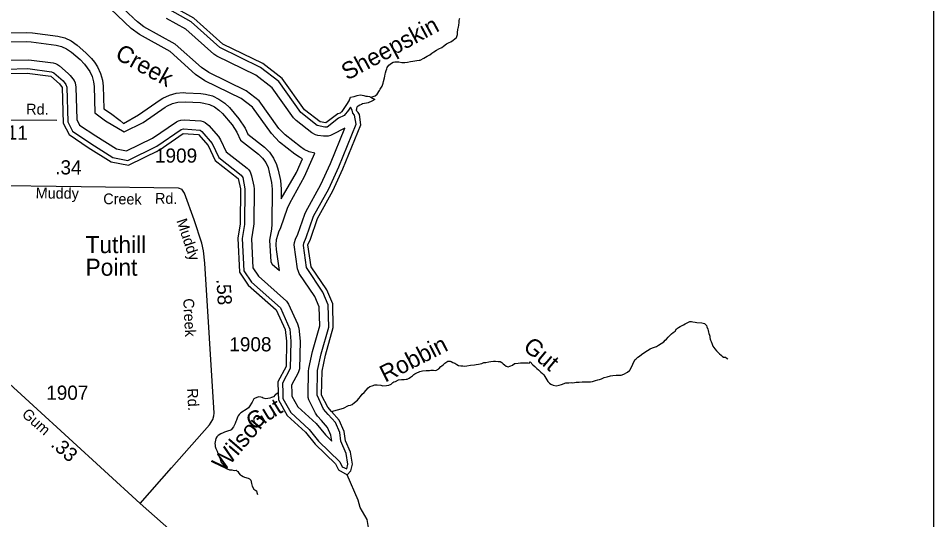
# Model space of a CAD drawing. Extents: x 2532689 to 2764727, y 536648 to 732970.
# Drawn here: x 2687851 to 2695930, y 582198 to 586621 of the extents above; entities that cross this region are included whole.
import ezdxf

# ---------------------------------------------------------------- set-up
doc = ezdxf.new("R2010")
doc.units = 0
for name, color, linetype in [('Exist Hydrographic Buffer Line', 7, 'Continuous'), ('Exist Hydrographic Creek Double Shore', 7, 'Continuous'), ('Exist Hydrographic Creek Single Shore', 7, 'Continuous'), ('Exist Hydrographic Creek Single Shore Label', 7, 'Continuous'), ('Exist Hydrographic Point Label', 7, 'Continuous'), ('Exist Road Secondary Mileage Hundredths English Label', 7, 'Continuous'), ('Exist Road Secondary Type 20 Attributed', 7, 'Continuous'), ('Exist Road Secondary Type 51 Attributed', 7, 'Continuous'), ('Exist Road Secondary Type 51 Label', 7, 'Continuous'), ('Exist Road Secondary Type 51 Number Label', 7, 'Continuous'), ('Map Preparation Inset Cut Line', 7, 'Continuous')]:
    doc.layers.add(name, color=color, linetype=linetype)

msp = doc.modelspace()

# ---------------------------------------------------------------- linework, layer by layer
at = {"layer": 'Exist Hydrographic Buffer Line'}
for points in [[(2688871.1, 586619.8), (2688536.5, 586939.4)], [(2689918.1, 585838.1), (2689819.3, 585914.1), (2689498.2, 586070.9), (2689415.8, 586126.3), (2689190.2, 586328.5), (2688921.6, 586477.3), (2688847.4, 586531.9), (2688481.3, 586881.5)], [(2690783.9, 585838.2), (2690765.6, 585810.1), (2690726, 585762.9), (2690678.1, 585740.7), (2690577.8, 585661.3), (2690557.9, 585659.4), (2690489.6, 585675.1), (2690345.7, 585789.6), (2690151.1, 586062.5), (2689988.9, 586187.4), (2689629.4, 586364.6), (2689376.8, 586591), (2689068.4, 586763.3)], [(2690169.1, 584776.2), (2690227.6, 584946.3), (2690247.7, 584991), (2690377.9, 585225.8), (2690457.8, 585404.6), (2690467.3, 585430.2), (2690418.3, 585443.5), (2690374.2, 585464.1), (2690341.8, 585486), (2690205.8, 585592.1), (2690150, 585650.3), (2689976.4, 585894.1), (2689861.5, 585982.4), (2689533.3, 586142.8), (2689469.3, 586185.9), (2689236.7, 586394.2), (2688960.3, 586547.2), (2688902.5, 586589.8), (2688874.1, 586617)], [(2690387.3, 584913.4), (2690520.8, 585154.2), (2690605.1, 585341.6), (2690731.8, 585652.8), (2690624.1, 585594.9), (2690605.1, 585586.1), (2690584.8, 585580.7), (2690545.6, 585580.3), (2690493.3, 585588.5), (2690473, 585593.9), (2690440.4, 585612.1), (2690304.2, 585718.3), (2690280.3, 585743.2), (2690092.8, 586006.4), (2689946.6, 586119), (2689603.4, 586286.6), (2689576.1, 586305.1), (2689330, 586525.4), (2689158.3, 586620.5)], [(2687737.4, 586493.2), (2687920.3, 586497.4), (2687975.7, 586494.3), (2688199.8, 586464.2), (2688260.7, 586448), (2688317.3, 586421.4), (2688371.4, 586383.2), (2688448.3, 586317.4), (2688497.1, 586266.5), (2688522.1, 586234.8), (2688551.1, 586192.1), (2688577.7, 586135.2), (2688593.9, 586074.6), (2688599.4, 586021.2), (2688604.4, 585822.7), (2688664.7, 585784.7), (2688748.9, 585718.7), (2688780.1, 585694.3), (2688912.6, 585770.7), (2689103.3, 585901.9), (2689127.5, 585917.1), (2689184, 585943.6), (2689244.9, 585959.8), (2689307.3, 585965.3), (2689328.2, 585964.7), (2689462.1, 585956.9), (2689503.9, 585952.1), (2689564.6, 585935.9), (2689621.4, 585909.3), (2689672.9, 585873.3), (2689713.7, 585833), (2689798.6, 585734.7), (2689852.3, 585652.2), (2689877.5, 585597.9), (2690023.9, 585483.6), (2690068, 585439.2), (2690104.1, 585387.9), (2690130.6, 585331), (2690144.9, 585281.3), (2690163.8, 585190.1), (2690171.4, 585114.3), (2690171, 585029.9), (2690306.1, 585261.7), (2690360.4, 585382.6), (2690334.2, 585394.9), (2690292.6, 585422.9), (2690156.6, 585529.1), (2690085, 585603.8), (2689918.1, 585838.1)], [(2687739, 586413.2), (2687922.2, 586417.3), (2687965, 586415), (2688185.9, 586385.4), (2688233, 586372.8), (2688277.3, 586352.2), (2688319.3, 586322.4), (2688396.4, 586256.6), (2688434.4, 586217.1), (2688459.4, 586185.3), (2688482, 586152.1), (2688502.5, 586107.8), (2688515.2, 586060.7), (2688519.3, 586019.2), (2688525.4, 585787.8), (2688621.2, 585717.6), (2688784.6, 585619.3), (2688953, 585701.4), (2689148.6, 585836), (2689167.4, 585847.8), (2689211.5, 585868.5), (2689258.9, 585881.1), (2689323.7, 585884.9), (2689457.6, 585877.1), (2689489.8, 585873.3), (2689537.1, 585860.7), (2689581.4, 585840.1), (2689621.4, 585812.1), (2689653.2, 585780.7), (2689738.1, 585682.4), (2689779.9, 585618.2), (2689813.4, 585546.6), (2689972.3, 585422.4), (2690006.9, 585387.9), (2690034.8, 585347.8), (2690055.3, 585303.6), (2690066.4, 585265), (2690085.5, 585173.8), (2690091.4, 585114.8), (2690089.4, 584806.2), (2690085, 584759.7), (2690068.6, 584665.4), (2690078.9, 584472.6), (2690092.6, 584452.1), (2690157.2, 584395.4), (2690129.3, 584580.2), (2690126.5, 584621.9), (2690130.6, 584670.5), (2690143.3, 584717.7), (2690151.9, 584738.5), (2690169.1, 584776.2)], [(2687742.5, 586253.3), (2687944.1, 586256.3), (2688158.2, 586227.9), (2688178.3, 586222.4), (2688197.3, 586213.7), (2688215.4, 586200.9), (2688292.3, 586135), (2688308.7, 586118.1), (2688343.3, 586072.1), (2688352.2, 586053.2)], [(2687744.4, 586173.3), (2687933.6, 586177), (2688144.4, 586149.1), (2688163.3, 586140.1), (2688245.9, 586068.6), (2688271, 586036.8), (2688279.4, 586013.1), (2688287.2, 585707.4), (2688330.2, 585624.9), (2688490.2, 585516.4), (2688686.4, 585394.2), (2688816.8, 585368.2), (2689074.1, 585493.4), (2689287.4, 585639.9), (2689309.5, 585645.3), (2689455.1, 585635.1), (2689471.5, 585623.7), (2689562.6, 585516.2), (2689620.6, 585392.7), (2689818.1, 585238.5), (2689831.6, 585216), (2689851.3, 585116.4), (2689848.8, 584801.1), (2689827.7, 584679.9), (2689842.7, 584394), (2689910.5, 584292.4), (2690163.8, 584065.6), (2690246.2, 583879.3), (2690257.3, 583773.1), (2690249.9, 583531.7), (2690182.7, 583403.4), (2690184.9, 583317.1), (2690186.1, 583266.3), (2690256.1, 583142.5), (2690417.4, 582994.9), (2690501.9, 582891.7), (2690687.7, 582708.4), (2690708.2, 582665.1), (2690750.2, 582647.8), (2690760.5, 582688.9), (2690743.9, 582783.3), (2690698.6, 582889.7), (2690688.3, 582965.8), (2690649.4, 583054.8), (2690586.4, 583125.3), (2690545.6, 583172.9), (2690488.4, 583297.8), (2690493.1, 583515.5), (2690523.9, 583660.7), (2690591.1, 583897.3), (2690586.6, 584093.4), (2690538.2, 584205.5), (2690395.9, 584423.4), (2690366.8, 584615.9), (2690370.1, 584638.6), (2690392.2, 584686.9), (2690457.4, 584874.6), (2690592.6, 585118.3), (2690678.7, 585310.1), (2690832.3, 585686.9), (2690819.3, 585765.9), (2690804.4, 585785.1), (2690796.4, 585810.8), (2690783.9, 585838.2)], [(2688352.2, 586053.2), (2688359.3, 586015.1), (2688366.7, 585728), (2688391.9, 585679.8), (2688533.8, 585583.4), (2688716.3, 585469.8), (2688806.1, 585451.9), (2689034, 585562.7), (2689247.4, 585709.2), (2689266.3, 585718.1), (2689286.6, 585723.5), (2689314.5, 585725.1), (2689462.1, 585715.7), (2689482.4, 585710.3), (2689501.3, 585701.5), (2689532, 585676.1), (2689617.1, 585577.7), (2689635.2, 585550.2), (2689684.8, 585444), (2689869.5, 585299.8), (2689884.3, 585285), (2689896.4, 585267.9), (2689909.9, 585232.3), (2689928.8, 585141.2), (2689931.5, 585115.9), (2689929.4, 584807.2), (2689927.6, 584787.3), (2689907.9, 584675.1), (2689921.4, 584420.2), (2689971.4, 584345.6), (2690219.4, 584126.3), (2690236.6, 584098.7), (2690315.7, 583924.6), (2690325.6, 583888), (2690337.5, 583772.1), (2690332.5, 583529.5), (2690320.7, 583494.6), (2690263.2, 583384.7), (2690264.9, 583319.1), (2690265.7, 583288.3), (2690319.4, 583193), (2690479.2, 583045.6), (2690561, 582946), (2690618, 582890.7)], [(2690618, 582890.7), (2690610.6, 582943.9), (2690581.1, 583011), (2690526.7, 583072), (2690492.1, 583110.7), (2690473.8, 583137.2), (2690415.6, 583255.9), (2690410.1, 583276.2), (2690408.4, 583299.4), (2690412.3, 583509.6), (2690415, 583532), (2690447, 583682.5), (2690510.9, 583907.5), (2690506.8, 584075.9), (2690467.7, 584166.9), (2690331.3, 584369.3), (2690322.7, 584388.3), (2690316.6, 584411.5), (2690286.4, 584621.9), (2690288, 584642.7), (2690297.3, 584671.9), (2690317.8, 584716.7), (2690378.9, 584894.3), (2690387.3, 584913.4)]]:
    msp.add_lwpolyline(points, dxfattribs=at)
at = {"layer": 'Exist Hydrographic Creek Double Shore'}
for points in [[(2690692.4, 585785.8), (2690670.1, 585778.6), (2690564, 585698.8), (2690514, 585706.7), (2690378.1, 585812.8), (2690180.2, 586090.5), (2690010, 586221.6), (2689656.1, 586394.4), (2689400.2, 586623.8), (2689096.1, 586792.2), (2688730.1, 587141.8), (2688661.2, 587240.8), (2688512.5, 587421.8)], [(2687745.4, 586133.3), (2687928.3, 586137.4), (2688137.5, 586109.7), (2688214.4, 586043.8), (2688239.4, 586012.1), (2688247.4, 585697.1), (2688299.5, 585597.4), (2688468.4, 585482.8), (2688671.4, 585356.4), (2688822.3, 585326.3), (2689094.4, 585458.8), (2689307.3, 585605.3), (2689441.4, 585597.5), (2689526.3, 585499.3), (2689588.4, 585367.1), (2689792.4, 585207.9), (2689811.3, 585116.7), (2689809.5, 584808), (2689787.3, 584682.3), (2689803.3, 584380.9), (2689880.4, 584265.8), (2690127.3, 584049.1), (2690206.4, 583875), (2690217.3, 583773.7), (2690214.4, 583550.3), (2690142.5, 583412.8), (2690144.9, 583316.2)], [(2690692.4, 585785.8), (2690702.7, 585795.7), (2690708, 585798.5), (2690733, 585833.4), (2690750.4, 585859.9), (2690771.4, 585892.7), (2690784.1, 585925.2), (2690814, 585932.2), (2690841.7, 585941), (2690869.6, 585945.9), (2690885.6, 585942.4), (2690901.8, 585940.9), (2690917.8, 585935.4), (2690933.8, 585933.9), (2690950.2, 585930.4), (2690962.1, 585926.8)], [(2690962.1, 585926.8), (2690996.9, 585905.8), (2690971.3, 585889), (2690939.9, 585876), (2690923.9, 585873.5), (2690907.9, 585871), (2690890.1, 585866.4), (2690880.2, 585862), (2690864.2, 585855.5), (2690850.9, 585845.1), (2690842.9, 585838.8), (2690840.3, 585833.4), (2690836.4, 585827.4), (2690836.4, 585817.3)], [(2690616.1, 583152), (2690581.5, 583190.8), (2690528.4, 583297), (2690532.5, 583507.3), (2690562.4, 583649.7), (2690631.3, 583892.2), (2690626.4, 584102.1), (2690573.3, 584224.8), (2690435.3, 584429.3), (2690406.4, 584621.9), (2690429.3, 584672.1), (2690492.3, 584855.2), (2690628.4, 585100.4), (2690715.4, 585294.4), (2690873.3, 585681.6), (2690861.4, 585772.7), (2690857.1, 585781.1), (2690851.5, 585790), (2690840.3, 585802.5), (2690836.4, 585810.8), (2690836.4, 585817.3)], [(2690144.9, 583316.2), (2690146.4, 583255.3), (2690224.5, 583117.3), (2690386.5, 582969.5), (2690472.4, 582864.6), (2690651.4, 582691.3), (2690677.4, 582636.5), (2690753.3, 582593.6)], [(2690753.3, 582593.6), (2690786.3, 582627.7), (2690801.5, 582687.4), (2690782.4, 582795), (2690738.3, 582895), (2690727.5, 582976.7), (2690683.4, 583076.7), (2690616.1, 583152)]]:
    msp.add_lwpolyline(points, dxfattribs=at)
at = {"layer": 'Exist Hydrographic Creek Single Shore'}
for points in [[(2690962.1, 585926.8), (2690982.2, 585931.4), (2690999.8, 585938), (2691017.4, 585952.5), (2691038.3, 585983.3), (2691046.1, 585997.5), (2691061.1, 586022.1), (2691070.3, 586048.4), (2691073.8, 586062.6), (2691082.8, 586096.9), (2691086.3, 586111.1), (2691089.8, 586129.2), (2691091.2, 586141.3), (2691098.8, 586161.6), (2691102.3, 586175.7), (2691107.8, 586187.9), (2691121.4, 586206.4), (2691133.1, 586216.8), (2691144.8, 586225.1), (2691160.5, 586233.7), (2691174.3, 586236.1), (2691192.3, 586236.6), (2691210.4, 586237.2), (2691236.6, 586232), (2691262.7, 586230.8), (2691286.7, 586233.6), (2691312.3, 586240.4), (2691334.4, 586243.1), (2691368.1, 586248.2), (2691388.2, 586250.8), (2691398, 586253.1), (2691429.6, 586268.2), (2691460.7, 586287.2), (2691482.5, 586299.9), (2691502.2, 586314.5), (2691519.8, 586325.1), (2691543.4, 586339.9), (2691562.9, 586352.5), (2691590.5, 586363.4), (2691604.1, 586375.9), (2691629.5, 586394.7), (2691653.1, 586407.4), (2691668.9, 586413.9), (2691690.6, 586428.7), (2691719.7, 586451.6), (2691728.7, 586478), (2691728.3, 586498), (2691731.6, 586518.2), (2691733.1, 586536.3), (2691734.9, 586544.3), (2691738.4, 586560.5), (2691741.7, 586584.7), (2691741, 586598.6), (2691744.5, 586616.8), (2691748.2, 586622.9)], [(2692496.9, 583460.9), (2692507.3, 583445.3), (2692524.3, 583417.7), (2692538.9, 583402.1), (2692551.2, 583392.5), (2692571.3, 583385.1), (2692597.6, 583379.9), (2692625.4, 583384.8), (2692645.1, 583391.4), (2692682.9, 583404.6), (2692710.9, 583405.5), (2692732.7, 583408.2), (2692746.8, 583404.6), (2692774.7, 583411.5), (2692802.6, 583412.3), (2692828.6, 583413.2), (2692866.6, 583414.3), (2692900.4, 583415.5), (2692920.3, 583418.1), (2692946.1, 583424.9), (2692966, 583431.5), (2692979.8, 583436), (2692997.6, 583440.5), (2693021.4, 583451.3), (2693047, 583458.1), (2693077, 583467.1), (2693098.9, 583469.8), (2693126.6, 583472.7), (2693154.9, 583471.6), (2693170.7, 583474), (2693196.3, 583482.8), (2693227.9, 583499.8), (2693245.3, 583514.5), (2693249.4, 583518.6), (2693260.7, 583537), (2693273.6, 583571.5), (2693285.1, 583589.9), (2693294.3, 583610.2), (2693304.2, 583618.5), (2693319.5, 583633), (2693333.3, 583641.5), (2693351.1, 583654.1), (2693372.6, 583668.8), (2693403.8, 583689.8), (2693427.4, 583704.6), (2693447.1, 583713.2), (2693482.8, 583726.3), (2693500.4, 583738.9), (2693525.8, 583753.8), (2693547.4, 583768.5), (2693559, 583780.8), (2693570.9, 583791.2), (2693586.1, 583807.8), (2693601.9, 583822.3), (2693615.4, 583836.7), (2693630.8, 583849.3), (2693648.6, 583861.9), (2693659.9, 583882.2), (2693677.6, 583892.8), (2693691.3, 583901.3), (2693720.8, 583918.2), (2693736.6, 583926.7), (2693760.2, 583937.5), (2693777.8, 583946.1), (2693793.8, 583946.6), (2693803.9, 583944.9), (2693826, 583939.6), (2693840.2, 583938), (2693884.3, 583935.3), (2693908.7, 583928.1), (2693925.1, 583910.6), (2693929.4, 583898.7), (2693936.1, 583878.8), (2693940.4, 583866.9), (2693942.9, 583853.1), (2693945.4, 583841), (2693951.5, 583827.2), (2693954.2, 583817.3), (2693954.4, 583805.3), (2693956.8, 583791.3), (2693959.1, 583781.3), (2693965.7, 583769.5), (2693974.3, 583745.7), (2693980.8, 583727.9), (2693997.6, 583706.4), (2694014.1, 583686.9), (2694032.9, 583667.4), (2694039.1, 583661.6), (2694053.4, 583649.9), (2694059.6, 583644.2), (2694063.7, 583640.3), (2694075.8, 583632.7), (2694092.2, 583631.1), (2694100.2, 583627.4), (2694114.3, 583617.9)], [(2690616.1, 583152), (2690721.3, 583180.9), (2690766.4, 583206.3), (2690782.4, 583208.8), (2690798.2, 583215.3), (2690819.7, 583232.1), (2690845.2, 583252.9), (2690856.7, 583267.3), (2690870.2, 583283.8), (2690887.4, 583304.3), (2690904.8, 583320.9), (2690922.5, 583339.5), (2690939.7, 583362.1), (2690953.4, 583372.6), (2690973.1, 583379.2), (2690999, 583388), (2691018.9, 583388.7), (2691050.8, 583385.6), (2691069.1, 583380.2), (2691100.9, 583383.2), (2691121, 583385.8), (2691140.7, 583394.5), (2691158.1, 583407), (2691166.1, 583413.3), (2691179.8, 583415.8), (2691205.7, 583430.6), (2691233.3, 583435.5), (2691255.5, 583436.1), (2691273.3, 583436.7), (2691283.4, 583439), (2691301.2, 583447.6), (2691312.7, 583456), (2691330.3, 583468.6), (2691342.2, 583478.9), (2691351.9, 583485.2), (2691361.7, 583489.5), (2691395.1, 583506.6), (2691419.1, 583511.4), (2691450.9, 583514.5), (2691480.8, 583515.4), (2691492.9, 583517.7), (2691516.9, 583516.5), (2691535, 583515.1), (2691562.4, 583529.9), (2691579.9, 583548.5), (2691587.7, 583554.8), (2691605.3, 583567.4), (2691616.8, 583577.8), (2691632.6, 583590.3), (2691642.4, 583596.6), (2691662.3, 583595.2), (2691670.3, 583593.5), (2691686.7, 583585.9), (2691702.9, 583578.4), (2691713.2, 583572.7), (2691721.4, 583567), (2691737.6, 583559.5), (2691755.6, 583556.1), (2691775.7, 583554.6), (2691787.8, 583553), (2691809.5, 583555.7), (2691843.6, 583560.8), (2691877.4, 583563.9), (2691893.4, 583566.4), (2691913.3, 583569), (2691941.2, 583575.9), (2691960.9, 583584.5), (2691978.9, 583585), (2692004.5, 583589.9), (2692022.6, 583594.4), (2692044.3, 583597.1), (2692062.6, 583595.7), (2692086.6, 583594.4), (2692102.6, 583592.9), (2692119, 583583.4), (2692129.2, 583573.7), (2692141.7, 583564.1), (2692155.9, 583552.5), (2692174.1, 583545.1), (2692189.9, 583551.6), (2692197.9, 583555.9), (2692211.6, 583562.3), (2692229.1, 583574.8), (2692235.2, 583575.1), (2692263.1, 583579.9), (2692283.2, 583582.5), (2692303.1, 583581.2), (2692317, 583581.6), (2692333, 583582.1), (2692349, 583580.6), (2692361.1, 583579), (2692368.9, 583591.2), (2692391.7, 583563.9), (2692410.1, 583548.4), (2692426.5, 583532.9), (2692440.9, 583521.4), (2692463.7, 583500), (2692478.2, 583486.4), (2692488.5, 583474.7), (2692496.9, 583460.9)], [(2690144.9, 583316.2), (2690123.4, 583302.5), (2690117.4, 583298.3), (2690103.9, 583281.8), (2690086.1, 583275.3), (2690070.1, 583270.8), (2690052.4, 583266.1), (2690034.4, 583265.6), (2690012.5, 583269), (2690002.2, 583274.6), (2689992, 583278.3), (2689973.9, 583281.8), (2689956.1, 583277.2), (2689936.4, 583268.5), (2689928.4, 583264.3), (2689922.9, 583252.1), (2689915.5, 583233.8), (2689909.7, 583225.6), (2689894.3, 583201.1), (2689882.9, 583184.7), (2689871.2, 583176.3), (2689847.6, 583161.5), (2689838, 583155.2), (2689816.4, 583140.5), (2689806.6, 583132.2), (2689800.8, 583126), (2689791.2, 583113.6), (2689785.7, 583101.5), (2689776.4, 583077.1), (2689770.9, 583062.9), (2689765.4, 583046.7), (2689755.9, 583028.3), (2689750.2, 583016.2), (2689729.1, 582991.5), (2689719.2, 582985.2), (2689707.3, 582982.7), (2689697.5, 582978.4), (2689669.6, 582969.5), (2689660, 582965.2), (2689638.2, 582954.5), (2689614.7, 582941.8), (2689603, 582929.3), (2689593.3, 582915), (2689591.9, 582901), (2689587, 582870.7), (2689587.2, 582856.7), (2689589.6, 582842.7), (2689594.4, 582824.9), (2689605.2, 582801.2), (2689613.8, 582773.3), (2689620.4, 582759.6), (2689631.3, 582733.8), (2689637.8, 582708), (2689652.6, 582690.4), (2689667.2, 582672.8), (2689679.7, 582659.1), (2689695.9, 582645.6), (2689714.1, 582638.2), (2689736.5, 582636.8), (2689756.3, 582633.5), (2689774.4, 582634), (2689782.6, 582626.3), (2689788.7, 582622.5), (2689797.2, 582608.7), (2689809.7, 582593), (2689819.9, 582587.4), (2689836.1, 582579.8), (2689848.4, 582574.2), (2689878.8, 582565.2), (2689884.7, 582561.3), (2689892.9, 582559.5), (2689903.2, 582547.8), (2689905.6, 582531.9), (2689910.1, 582518), (2689912.4, 582506), (2689914.9, 582494.1), (2689929.6, 582468.5), (2689938, 582462.7), (2689946.2, 582457), (2689954.2, 582451.2), (2689956.7, 582439.3), (2689958.9, 582429.3), (2689963.2, 582421.5)], [(2692527.2, 580902.1), (2692147.5, 581077.1), (2691542.4, 581272.6), (2691306.3, 581417.4), (2691202.4, 581570.8), (2691072.4, 581795.4), (2691054.3, 581850.5), (2691010.4, 581927.6), (2690991.4, 582035.1), (2690948.5, 582092.5), (2690929.5, 582200.1), (2690868.3, 582306), (2690850.5, 582370.9), (2690753.3, 582593.6)]]:
    msp.add_lwpolyline(points, dxfattribs=at)
at = {"layer": 'Exist Road Secondary Type 20 Attributed'}
for points in [[(2687517.6, 585147.9), (2688404.4, 585137.6), (2689262.1, 585126.8), (2689294.4, 585115.3)], [(2688926.2, 582341.6), (2689203.1, 582654.6), (2689537.2, 583034.4), (2689568.1, 583080.9), (2689575.4, 583113.4), (2689579, 583137.2), (2689498.4, 584461.3), (2689485.8, 584569.1), (2689471.4, 584637.7), (2689402.9, 584843.2), (2689319.2, 585079.2), (2689294.4, 585115.3)]]:
    msp.add_lwpolyline(points, dxfattribs=at)
at = {"layer": 'Exist Road Secondary Type 51 Attributed'}
msp.add_line((2688926.2, 582341.6), (2687647.7, 583510.5), dxfattribs=at)
for points in [[(2687515.9, 585726.1), (2687765.1, 585725.1), (2688190.2, 585721.7)], [(2691231.8, 580229.9), (2690048.7, 581351.9), (2689738.3, 581622.7), (2688926.2, 582341.6)]]:
    msp.add_lwpolyline(points, dxfattribs=at)
at = {"layer": 'Map Preparation Inset Cut Line'}
msp.add_lwpolyline([(2682347.2, 562752.7), (2695930.4, 562752.7), (2695930.4, 589310.3), (2682347.2, 589310.3)], close=True, dxfattribs=at)

# ---------------------------------------------------------------- texts
at = {"layer": 'Exist Hydrographic Creek Single Shore Label'}
for s, rotation, p in [('Sheepskin', 28.32294, (2690753.8, 586070.3)), ('Creek', 331.03001, (2688695.8, 586271.3)), ('Robbin', 27.0556, (2691089.5, 583405.8)), ('Gut', 320.00709, (2692296.7, 583707.8)), ('Gut', 31.46149, (2689919.3, 582982.3)), ('Wilson', 49.47711, (2689662.4, 582611.3))]:
    msp.add_text(s, height=150, rotation=rotation, dxfattribs=at).set_placement(p)
at = {"layer": 'Exist Hydrographic Point Label'}
for s, p in [('Tuthill', (2688444.5, 584549.5)), ('Point', (2688444.5, 584350.2))]:
    msp.add_text(s, height=150, dxfattribs=at).set_placement(p)
at = {"layer": 'Exist Road Secondary Mileage Hundredths English Label'}
for s, rotation, p in [('.11', 359.54504, (2687702.4, 585551.4)), ('.34', 359.3331, (2688176.2, 585245)), ('.58', 273.48521, (2689598.8, 584319.4)), ('.33', 318.39495, (2688130.6, 582851.5))]:
    msp.add_text(s, height=125, rotation=rotation, dxfattribs=at).set_placement(p)
at = {"layer": 'Exist Road Secondary Type 51 Label'}
for s, rotation, p in [('Rd.', 359.54504, (2687920.1, 585773.1)), ('Muddy', 359.38976, (2688003.8, 585032.8)), ('Creek', 359.38976, (2688600.4, 584981.6)), ('Rd.', 359.38976, (2689056.9, 584986.1)), ('Muddy', 288.51525, (2689245.4, 584836.1)), ('Creek', 273.03134, (2689305.9, 584148.1)), ('Rd.', 273.03134, (2689340.5, 583355)), ('Gum', 318.39495, (2687875.1, 583118))]:
    msp.add_text(s, height=95, rotation=rotation, dxfattribs=at).set_placement(p)
at = {"layer": 'Exist Road Secondary Type 51 Number Label'}
for s, p in [('1909', (2689057.5, 585347.8)), ('1908', (2689713.7, 583683)), ('1907', (2688097.5, 583256))]:
    msp.add_text(s, height=125, dxfattribs=at).set_placement(p)

doc.saveas('drawing.dxf')
